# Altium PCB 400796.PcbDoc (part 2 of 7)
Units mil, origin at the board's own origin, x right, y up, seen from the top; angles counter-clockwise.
Board outline 2086.61 x 2086.61 mil, 6 copper layers (Top Layer, Mid Layer 1, Mid Layer 2, Mid Layer 3, Mid Layer 4, Bottom Layer), stack 58.818 mil thick; 313 components, 234 nets, 1244 pads, 2538 vias.
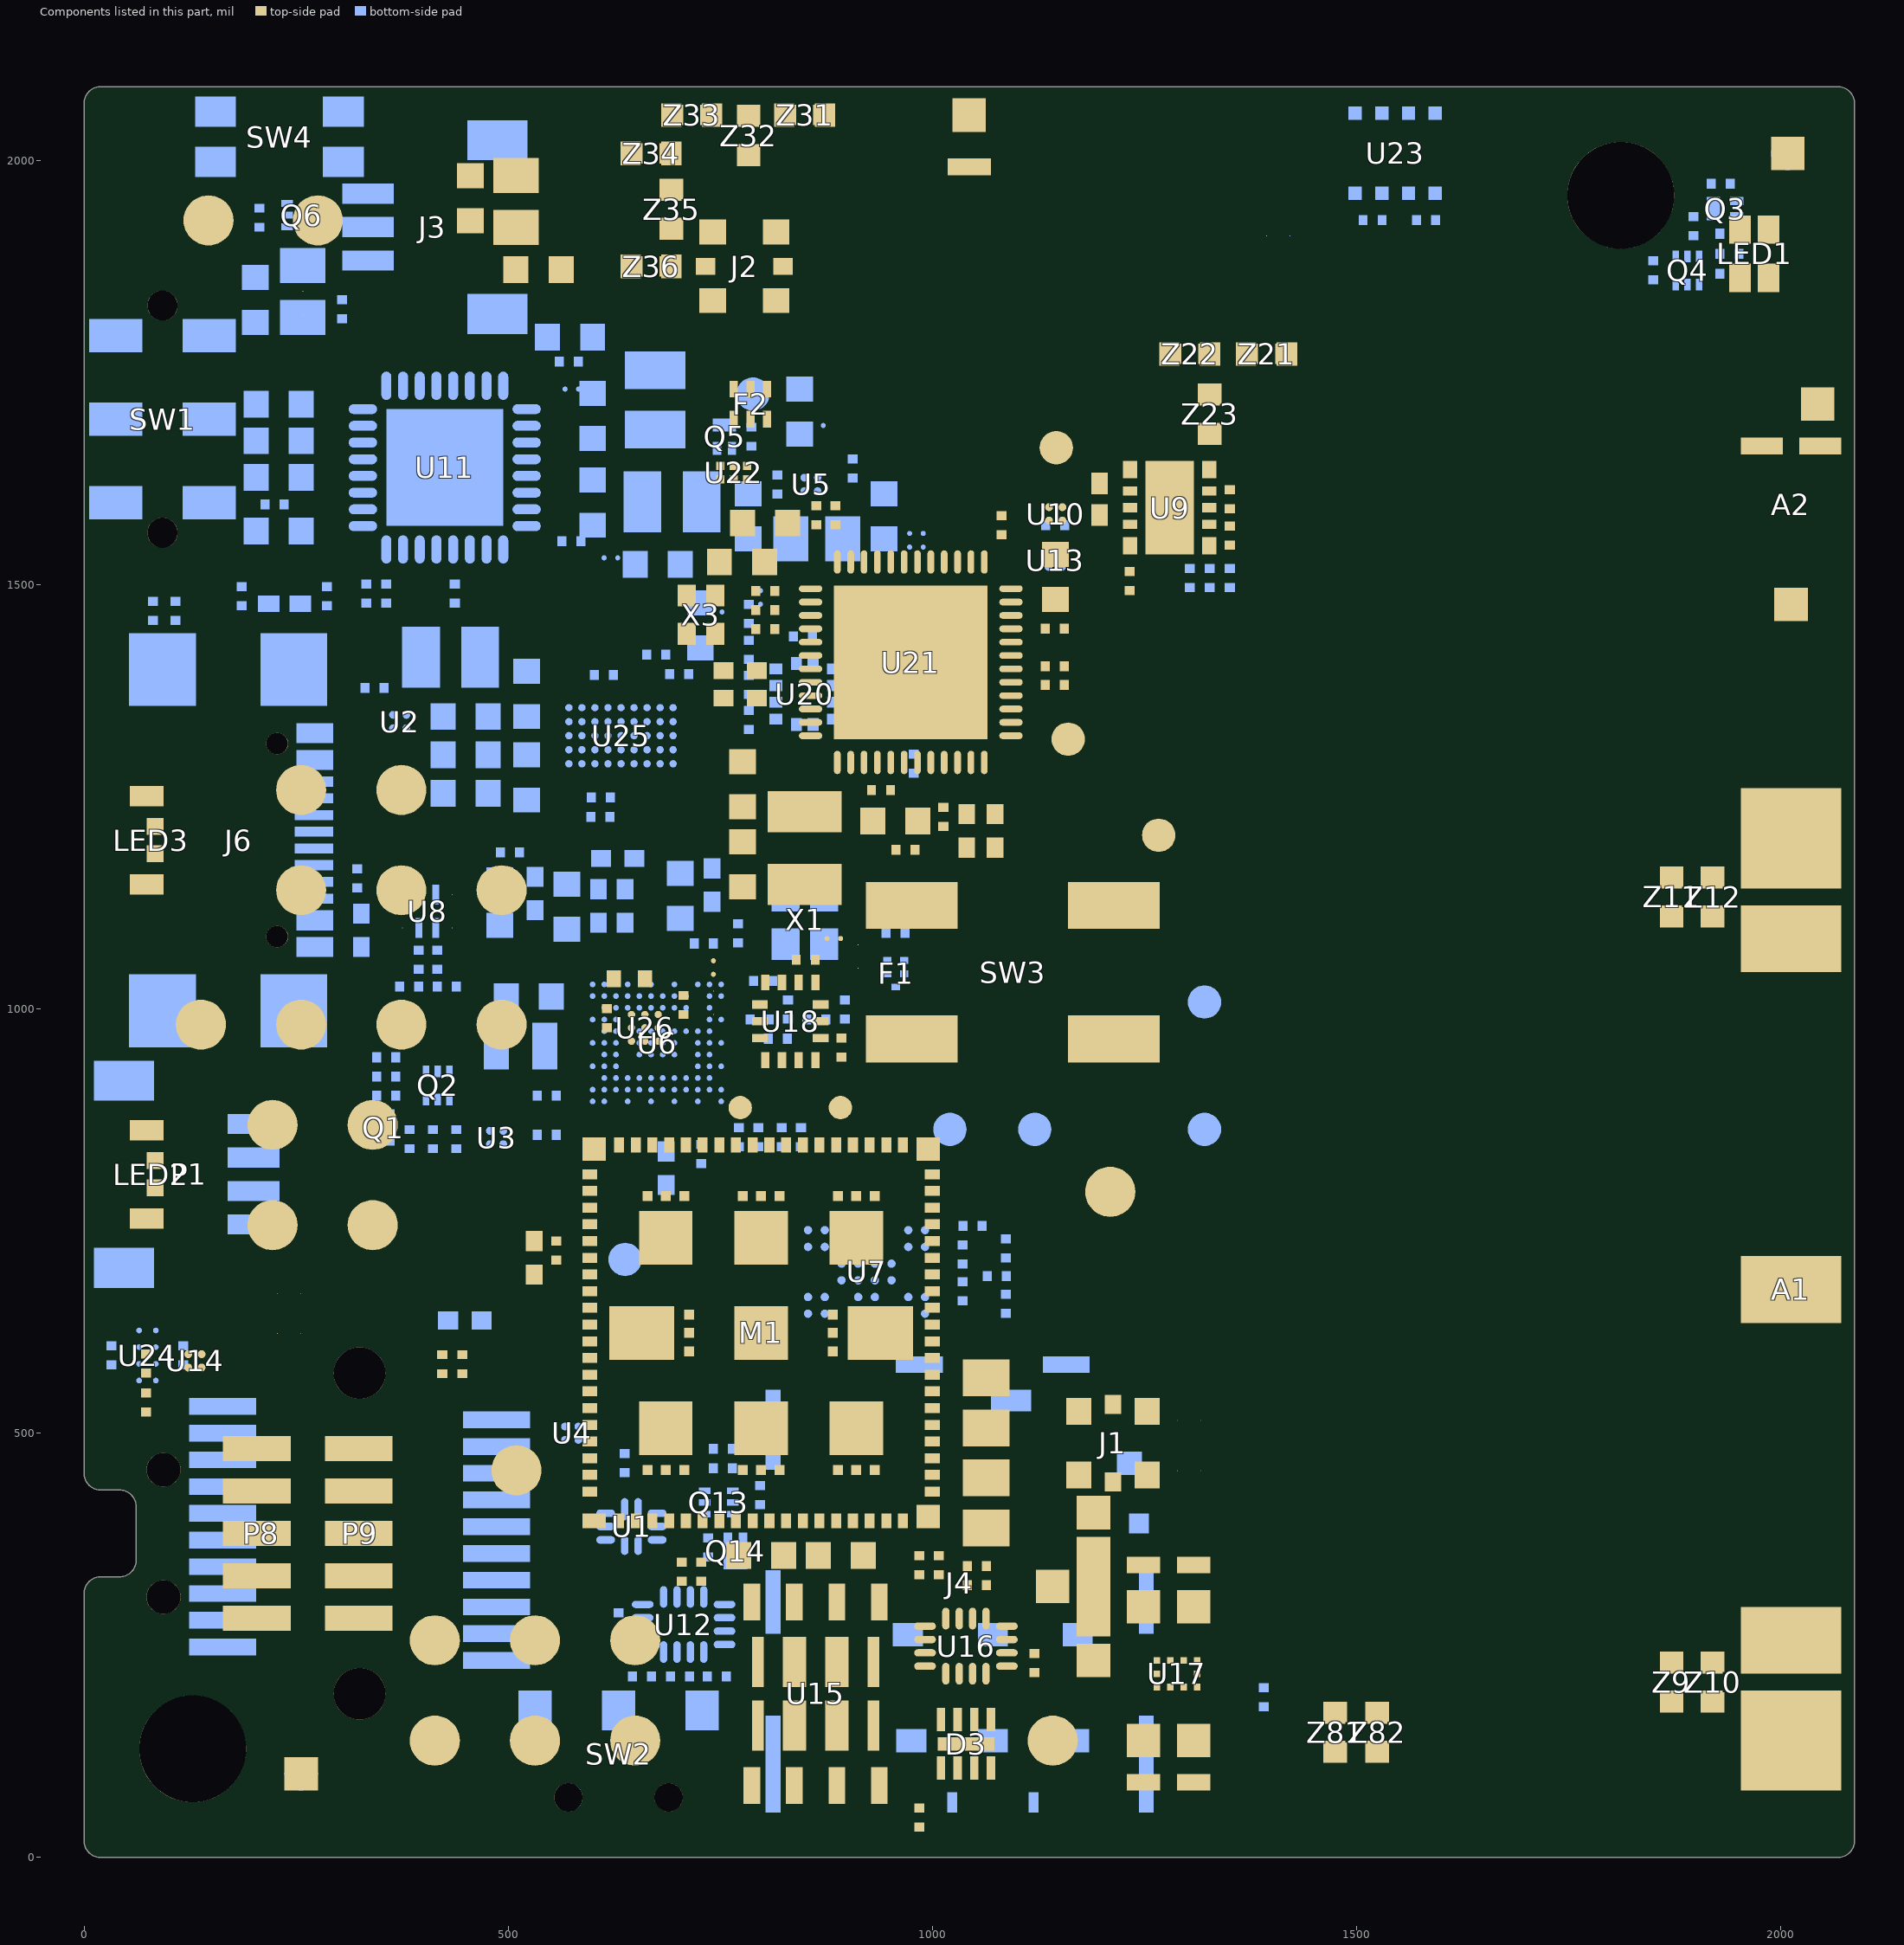
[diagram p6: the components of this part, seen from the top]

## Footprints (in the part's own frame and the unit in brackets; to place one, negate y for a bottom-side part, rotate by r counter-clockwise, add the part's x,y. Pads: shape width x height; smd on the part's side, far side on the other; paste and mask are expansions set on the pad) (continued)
COAXIAL-SWF [mm]
  rect 0.5x0.58 smd: 1(0,1.16) 3(0,-1.16)
  rect 0.75x0.8 smd: 2(-1.025,-0.95) 2(-1.025,0.95) 2(1.025,-0.95) 2(1.025,0.95)
  Top Layer pour cut-out: 0.65,-0.55 -0.65,-0.55 -0.65,-1.35 0.65,-1.35
  Top Layer pour cut-out: -0.65,0.55 0.65,0.55 0.65,1.35 -0.65,1.35
  silkscreen extent -1.25,-1.25 1.25,1.25, body extent -1.26,-1.3 1.26,1.3, height 1.55
DFN65P100X40-3L [mm] "DFN, 3-Leads, Body 0.60x1.00mm, Pitch 0.65mm, IPC High Density"
  rect 0.4x0.25 smd mask+0.05: 1(-0.35,0.225) 2(-0.35,-0.225)
  rect 0.4x0.7 smd mask+0.065: 3(0.35,0)
  silkscreen extent -0.57,0.58 -0.48,0.67, body extent -0.53,-0.33 0.53,0.33, height 0.4
Fiducial_Round-Square [mm] "Fiducial Mark"
  rect 1x1 smd paste-2539.97 mask+0.5: 0(0,0)
  round 1 smd far side paste-2539.97 mask+0.5: 0(0,0)
  Top Layer keep-out lines w0.01: 1,1 -1,1 -1,-1 1,-1 1,1
  Bottom Layer keep-out circle w0.01: c0,0 r1
HDR_2x5-SMD-1.27mm-ANG [mm] "Pin Header Angled, 1.27mm SMD, FTSH-105 series, \"SWD\" version"
  round 1.02 hole 1.02 unplated: 0(-1.905,-4.32) 0(1.905,-4.32)
  rect 0.76x2.03 smd: 1(-2.54,-1.525) 2(-2.54,1.525) 3(-1.27,-1.525) 4(-1.27,1.525) 5(0,-1.525) 6(0,1.525) 7(1.27,-1.525) 8(1.27,1.525) 9(2.54,-1.525) 10(2.54,1.525)
  silkscreen extent -3.17,-5.57 3.17,-3.07, body extent -3.17,-8.63 3.17,2.27, height 3.41
INDC0603X03L_C [mm] "Chip Inductor, 2-Leads, Body 0.6x0.3mm, IPC High Density"
  rect 0.27x0.3 smd: 1(-0.285,0) 2(0.285,0)
  silkscreen extent -0.49,-0.22 0.49,0.22, body extent -0.31,-0.16 0.31,0.16, height 0.26
INDC1005X04L [mm] "Chip Inductor, 2-Leads, Body 1.0x0.5mm, IPC High Density"
  rect 0.65x0.5 smd: 1(-0.475,0) 2(0.475,0)
  silkscreen extent -0.9,-0.35 0.9,0.35, body extent -0.5,-0.28 0.5,0.32, height 0.5
INDC1005X04L_WW [mm] "Chip Inductor, 2-Leads, Body 1.0x0.5mm, IPC High Density"
  rect 0.65x0.5 smd: 1(-0.475,0) 2(0.475,0)
  silkscreen extent -0.9,-0.35 0.9,0.35, body extent -0.5,-0.3 0.5,0.3, height 0.51
INDC1608X06L [mm] "Chip Inductor, 2-Leads, Body 1.6x0.8mm, IPC High Density"
  rect 0.75x0.8 smd: 1(-0.675,0) 2(0.675,0)
  silkscreen extent -1.17,-0.5 1.17,0.5, body extent -0.8,-0.4 0.8,0.4, height 0.8
INDC2012X11L [mm] "Chip Inductor, 2-Leads, Body 2.0x1.3mm, IPC High Density"
  rect 1.05x1.35 smd: 1(-0.775,0) 2(0.775,0)
  silkscreen extent -1.43,-0.77 1.43,0.77, body extent -1,-0.63 1,0.63, height 1.25
INDC2016X10N [mm] "Chip Inductor, 2-Leads, Body 2.00x1.60mm, IPC Medium Density"
  rect 1.13x1.82 smd: 1(-0.885,0) 2(0.885,0)
  silkscreen extent -1.65,-1.14 1.65,1.14, body extent -1.1,-0.9 1.1,0.9, height 1
INDC2520X10N [mm] "Chip Inductor, 2-Leads, Body 2,50x2,00mm, IPC Medium Density"
  rect 1.23x2.22 smd: 1(-1.085,0) 2(1.085,0)
  silkscreen extent -0.1,-1.01 0.1,1.01, body extent -1.25,-1.1 1.25,1.1, height 1.98
L-KLS7-TS5401A-1.35-250-T [mm]
  rect 1.225x0.9 smd: 1(-1.913,0.75) 1(1.913,0.75) 2(-1.913,-0.75) 2(1.913,-0.75)
  silkscreen extent -2.1,-2.15 1.75,1.84
L-KLS7-TS6616B-2.5-160-T [mm] "6.2×6.4mm TACT Switch, without ground connector"
  rect 2.75x1.4 smd: 1(-3.025,2) 1(3.025,2) 2(-3.025,-2) 2(3.025,-2)
  silkscreen extent -3,-3 3,3, body extent -3.6,-3.1 3.6,3.1, height 2.5
LabelSilk_12x38 [mil] "PCA version label, stick-on, 12x38mm"
  silkscreen extent 0,0 1496,472, body extent 0,-2 1496,472
LED_RGB_0606 [mm]
  rect 0.65x0.85 smd paste+0: 1(-0.425,0.725) 2(0.425,0.725) 3(0.425,-0.725) 4(-0.425,-0.725)
  silkscreen extent -0.75,-0.8 0.75,0.8, body extent -0.75,-0.8 0.75,0.8, height 0.35
LGA50P220X230X97-12N [mm] "LGA, 12-Leads, Body 2,20x2,30mm, Pitch 0,50mm, IPC Medium Density"
  rect 0.39x0.33 smd mask+0.05: 1(-0.86,0.75) 2(-0.86,0.25) 3(-0.86,-0.25) 4(-0.86,-0.75) 7(0.86,-0.75) 8(0.86,-0.25) 9(0.86,0.25) 10(0.86,0.75)
  rect 0.33x0.39 smd mask+0.05: 5(-0.25,-0.91) 6(0.25,-0.91) 11(0.25,0.91) 12(-0.25,0.91)
  silkscreen extent -1.4,-1.17 1.13,1.45, body extent -1.15,-1.2 1.15,1.2, height 0.97
"LGA50P1210X1110X130-113N - 98A0113SP002-O01" [mm]
  rect 0.7x0.45 smd paste-2539.97 mask-5: 1(-5,-5.625)
  rect 0.3x0.45 smd mask+0.05: 2(-4.25,-5.625) 3(-3.75,-5.625) 4(-3.25,-5.625) 5(-2.75,-5.625) 6(-2.25,-5.625) 7(-1.75,-5.625) 8(-1.25,-5.625) 9(-0.75,-5.625) 10(-0.25,-5.625) 11(0.25,-5.625) 12(0.75,-5.625) 13(1.25,-5.625) 14(1.75,-5.625) 15(2.25,-5.625) 16(2.75,-5.625) 17(3.25,-5.625) 18(3.75,-5.625) 19(4.25,-5.625) 42(4.25,5.625) 43(3.75,5.625) 44(3.25,5.625) 45(2.75,5.625) 46(2.25,5.625) 47(1.75,5.625) 48(1.25,5.625) 49(0.75,5.625) 50(0.25,5.625) 51(-0.25,5.625) 52(-0.75,5.625) 53(-1.25,5.625) 54(-1.75,5.625) 55(-2.25,5.625) 56(-2.75,5.625) 57(-3.25,5.625) 58(-3.75,5.625) 59(-4.25,5.625)
  rect 0.7x0.7 smd mask+0.05: 20(5,-5.5) 41(5,5.5) 60(-5,5.5)
  rect 0.45x0.3 smd mask+0.05: 21(5.125,-4.75) 22(5.125,-4.25) 23(5.125,-3.75) 24(5.125,-3.25) 25(5.125,-2.75) 26(5.125,-2.25) 27(5.125,-1.75) 28(5.125,-1.25) 29(5.125,-0.75) 30(5.125,-0.25) 31(5.125,0.25) 32(5.125,0.75) 33(5.125,1.25) 34(5.125,1.75) 35(5.125,2.25) 36(5.125,2.75) 37(5.125,3.25) 38(5.125,3.75) 39(5.125,4.25) 40(5.125,4.75) 61(-5.125,4.75) 62(-5.125,4.25) 63(-5.125,3.75) 64(-5.125,3.25) 65(-5.125,2.75) 66(-5.125,2.25) 67(-5.125,1.75) 68(-5.125,1.25) 69(-5.125,0.75) 70(-5.125,0.25) 71(-5.125,-0.25) 72(-5.125,-0.75) 73(-5.125,-1.25) 74(-5.125,-1.75) 75(-5.125,-2.25) 76(-5.125,-2.75) 77(-5.125,-3.25) 78(-5.125,-3.75) 79(-5.125,-4.25) 80(-5.125,-4.75)
  rect 0.3x0.3 smd mask+0.05: 81(-3.4,-4.1) 82(-2.85,-4.1) 83(-2.3,-4.1) 84(-0.55,-4.1) 85(0,-4.1) 86(0.55,-4.1) 87(2.3,-4.1) 88(2.85,-4.1) 89(3.4,-4.1) 90(2.15,-0.55) 91(2.15,0) 92(2.15,0.55) 93(3.4,4.1) 94(2.85,4.1) 95(2.3,4.1) 96(0.55,4.1) 97(0,4.1) 98(-0.55,4.1) 99(-2.3,4.1) 100(-2.85,4.1) 101(-3.4,4.1) 102(-2.15,0.55) 103(-2.15,0) 104(-2.15,-0.55)
  rect 1.6x1.6 smd mask+0.05: 105(-2.85,-2.85) 106(0,-2.85) 107(2.85,-2.85) 109(2.85,2.85) 110(0,2.85) 111(-2.85,2.85) 113(0,0)
  rect 1.95x1.6 smd mask+0.05: 108(3.575,0) 112(-3.575,0)
  Top Layer region: -5.35,-5.15 -5.35,-5.85 -4.65,-5.85 -4.65,-5.4 -4.9,-5.15
  silkscreen extent -5.99,-6.5 -5.69,-6.2, body extent -5.6,-6.1 5.6,6.1, height 1.21
MountingHole_3.2_M3 [mm] "Mounting hole, 3.2mm, M3,no annular"
  round 3.2 hole 3.2 unplated mask+0: ""(0,0)
NN02-101_Corner [mm] "NANO mXTEND  Miniature and high-efficiency Bluetooth/WI-FI Antenna"
  rect 0.5x1.3 smd mask+0.075: 0(-0.65,0)
  rect 1x1 smd mask+0.075: 1(0.9,0)
  Top Layer region: 0.4,-0.5 1.4,-0.5 1.4,0.5 0.4,0.5
  Multi-Layer pour cut-out: -3.25,-4 -3.25,1 1.75,1 1.75,-4
  silkscreen extent -1.32,-1.07 1.83,1.08, body extent -1.25,-1 1.75,1, height 0.8
NN03-310_RF_ALT1 [mm] "NN03-310_RF"
  rect 2x3 smd: 0(0,0) 2(10.5,0) 4(-10.5,0)
  rect 3x3 smd: 1(13.5,0) 3(-13.5,0)
  Top Layer region: 14,-0.5 15,-0.5 15,-6.504 14,-6.504
  Top Layer region: 13,-0.5 12,-0.5 12,-4 13,-4
  Top Layer region: 11.5,-0.5 10.5,-0.5 10.5,-4 11.5,-4
  Top Layer region: -12,-0.5 -13,-0.5 -13,-4 -12,-4
  Top Layer region: -10.5,-0.5 -11.5,-0.5 -11.5,-4 -10.5,-4
  Multi-Layer pour cut-out: -25,2 25,2 25,-10.5 -25,-10.5
  silkscreen extent -15,-1.6 15,1.6, body extent -15,-1.5 15,1.5, height 1
NN03-320 [mm]
  rect 1x1 smd: 1(-3,0) 4(3,-0.8)
  rect 0.5x1.25 smd: 2(1.75,-0.875) 3(1.75,0.875)
  Multi-Layer pour cut-out: -3.5,1.5 3.5,1.5 3.5,-1.5 -3.5,-1.5
  silkscreen extent -3.6,-1.6 3.6,1.6, body extent -3.5,-1.5 3.5,1.5, height 2.01
Nordic_QFN50P500X500X90-33N [mm] "QFN32 5x5x0.85mm, 0.5mm pitch - Medium Density"
  oval 0.85x0.3 smd mask+0.076: 1(-2.45,1.75) 2(-2.45,1.25) 3(-2.45,0.75) 4(-2.45,0.25) 5(-2.45,-0.25) 6(-2.45,-0.75) 7(-2.45,-1.25) 8(-2.45,-1.75) 17(2.45,-1.75) 18(2.45,-1.25) 19(2.45,-0.75) 20(2.45,-0.25) 21(2.45,0.25) 22(2.45,0.75) 23(2.45,1.25) 24(2.45,1.75)
  oval 0.3x0.85 smd mask+0.076: 9(-1.75,-2.45) 10(-1.25,-2.45) 11(-0.75,-2.45) 12(-0.25,-2.45) 13(0.25,-2.45) 14(0.75,-2.45) 15(1.25,-2.45) 16(1.75,-2.45) 25(1.75,2.45) 26(1.25,2.45) 27(0.75,2.45) 28(0.25,2.45) 29(-0.25,2.45) 30(-0.75,2.45) 31(-1.25,2.45) 32(-1.75,2.45)
  rect 3.5x3.5 smd: 33(0,0)
  silkscreen extent -3.43,-2.57 2.57,2.62, body extent -2.5,-2.5 2.5,2.5, height 0.9
OVSRRGBCC3_Side [mil] "Optek's OVSRRGBCC3 RGB full-color 1204 SMD, RGB LED"
  rect 20x20 smd: 1(5,-16) 2(5,16)
  rect 40x24 smd: 3(-5,52) 4(-5,-52)
  silkscreen extent -68,-68 18,68, body extent -65,-63 16,63, height 31
PQFN40P110X150X50-10N [mm] "PQFN, 10-Leads, Body 1,10x1,50mm, Pitch 0,40mm, IPC Medium Density"
  rect 0.2x0.2 smd mask+0.05: 1(-0.4,0.6) 2(-0.4,0.2) 3(-0.4,-0.2) 4(-0.4,-0.6) 5(0,-0.6) 6(0.4,-0.6) 7(0.4,-0.2) 8(0.4,0.2) 9(0.4,0.6) 10(0,0.6)
  silkscreen extent -0.9,-0.8 0.6,1.1, body extent -0.55,-0.75 0.55,0.75, height 0.5
QFN40P600X600X60-48N [mm] "QFN, 48-Leads, Body 6.1x6.1mm (max), Pitch 0.40mm, IPC Medium Density"
  oval 0.7x0.2 smd: 1(-3,2.2) 2(-3,1.8) 3(-3,1.4) 4(-3,1) 5(-3,0.6) 6(-3,0.2) 7(-3,-0.2) 8(-3,-0.6) 9(-3,-1) 10(-3,-1.4) 11(-3,-1.8) 12(-3,-2.2) 25(3,-2.2) 26(3,-1.8) 27(3,-1.4) 28(3,-1) 29(3,-0.6) 30(3,-0.2) 31(3,0.2) 32(3,0.6) 33(3,1) 34(3,1.4) 35(3,1.8) 36(3,2.2)
  oval 0.2x0.7 smd: 13(-2.2,-3) 14(-1.8,-3) 15(-1.4,-3) 16(-1,-3) 17(-0.6,-3) 18(-0.2,-3) 19(0.2,-3) 20(0.6,-3) 21(1,-3) 22(1.4,-3) 23(1.8,-3) 24(2.2,-3) 37(2.2,3) 38(1.8,3) 39(1.4,3) 40(1,3) 41(0.6,3) 42(0.2,3) 43(-0.2,3) 44(-0.6,3) 45(-1,3) 46(-1.4,3) 47(-1.8,3) 48(-2.2,3)
  rect 4.6x4.6 smd: 49(0,0)
  silkscreen extent -4.02,-3.05 3.05,3.05, body extent -3.02,-3.02 3.02,3.02, height 0.86
RESC0603X03L_C [mm] "Chip Resistor, 2-Leads, Body 0.6x0.3mm, IPC High Density"
  rect 0.27x0.3 smd: 1(-0.285,0) 2(0.285,0)
  silkscreen extent -0.49,-0.22 0.49,0.22, body extent -0.3,-0.15 0.3,0.15, height 0.23
RESC0603X03L_C_NC [mm] "Chip Resistor, 2-Leads, Body 0.6x0.3mm, IPC High Density"
  rect 0.27x0.3 smd: 1(-0.285,0) 2(0.285,0)
  silkscreen extent -0.49,-0.22 0.49,0.22
RESC1005X04L [mm] "Chip Resistor, 2-Leads, Body 1.0x0.5mm, IPC High Density"
  rect 0.6x0.55 smd mask+0.05: 1(-0.5,0) 2(0.5,0)
  silkscreen extent -0.87,-0.38 0.88,0.38, body extent -0.5,-0.25 0.5,0.25, height 0.3
SAFFB2G45MA0F0A [mm] "SOT23, 5-Leads, Body 2,90x2,80mm, Pitch 0,95mm, IPC Medium Density"
  rect 0.2x0.25 smd mask+0.065: 1(-0.4,0) 2(0,-0.25) 3(0.4,-0.25) 4(0.4,0.25) 5(0,0.25)
  silkscreen extent -0.81,-0.71 0.61,0.51, body extent -0.55,-0.45 0.55,0.45, height 0.5
SF72S006VBxR2500 [mm]
  rect 0.45x2.9 smd: 0(-11.175,1.9) 0(0,1.9)
  rect 0.45x1.9 smd: 0(-11.175,6.75) 0(0,6.75)
  rect 0.75x0.7 smd: 0(-10.675,10.9)
  rect 1.4x0.5 smd: 0(-8.78,13.85) 0(-4.38,13.85)
  rect 0.3x0.6 smd: 0(-7.8,0.75) 0(-5.36,0.75)
  rect 0.45x2.4 smd: 0(0,11.9)
  rect 0.9x0.7 smd: C1(-4.14,2.6) C2(-6.58,2.6) C3(-9.02,2.6) C5(-4.04,5.77) C6(-6.58,5.77) C7(-9.12,5.77)
  rect 0.6x0.6 smd: CSW(-10.95,9.1)
  rect 1.2x0.65 smd: DSW(-7.13,12.775)
  Top Layer pour cut-out: -10.084,9.5 -3.073,9.5 -3.073,-0.025 -10.084,-0.025
  Top Layer pour cut-out: -8.407,13.106 -3.48,13.106 -3.48,9.855 -8.407,9.855
  Top Layer keep-out region: -3.531,2.091 -3.531,3.107 -3.073,3.107 -3.073,2.091
  Top Layer keep-out region: -3.429,5.266 -3.429,6.282 -3.073,6.282 -3.073,5.266
  Top Layer keep-out region: -8.407,2.091 -8.407,3.107 -7.188,3.107 -7.188,2.091
  Top Layer keep-out region: -5.969,2.091 -5.969,3.107 -4.75,3.107 -4.75,2.091
  Top Layer keep-out region: -5.969,5.266 -5.969,6.282 -4.648,6.282 -4.648,5.266
  Top Layer keep-out region: -8.509,5.266 -8.509,6.282 -7.188,6.282 -7.188,5.266
  Top Layer keep-out region: -7.468,0.262 -7.468,1.278 -5.69,1.278 -5.69,0.262
  Top Layer keep-out region: -8.4,9.85 -8.4,13.099 -7.899,13.1 -7.899,12.302 -6.375,12.302 -6.375,13.1 -3.48,13.106 -3.48,9.855
  Top Layer keep-out region: -10.084,-0.025 -10.084,9.5 -3.073,9.5 -3.073,6.282 -9.728,6.282 -9.728,5.266 -3.073,5.266 -3.073,3.107 -9.627,3.107 -9.627,2.091 -3.073,2.091 -3.073,1.202 -8.128,1.202 -8.128,0.287 -5.029,0.287 -5.029,1.253 -3.073,1.253 -3.073,-0.025
  silkscreen extent -11.3,-0.67 0.67,14.53, body extent -11.2,0.05 0.02,14.4, height 1.25
SKY65943-11 [mm]
  rect 0.425x0.515 smd mask+0.05: 1(-1.188,1.144) 5(-1.188,-1.144) 6(1.188,-1.144) 10(1.188,1.144)
  rect 0.425x0.275 smd mask+0.05: 2(-1.188,0.5) 3(-1.188,0) 4(-1.188,-0.5) 7(1.188,-0.5) 8(1.188,0) 9(1.188,0.5)
  rect 1.45x2.802 smd paste-2 mask-5: 11(0,0)
  rect 1.55x2.487 on Top Solder: ""(0,0)
  Top Layer region: -0.988,0.887 -0.713,0.887 -0.713,1.4 -0.988,1.4
  Top Layer region: 0.713,-1.4 0.988,-1.4 0.988,-0.887 0.713,-0.887
  Top Layer region: 0.713,0.362 0.988,0.362 0.988,0.637 0.713,0.637
  Top Layer region: -0.712,-0.362 -0.987,-0.362 -0.987,-0.637 -0.712,-0.637
  silkscreen extent -1.65,-1.3 1.3,1.65, body extent -1.25,-1.25 1.25,1.25, height 0.71
SM03B-SRSS-TB [mm] "JST, SH connector, side entry SMD, 1mm pitch"
  rect 1.2x1.8 smd: 0(-2.6,-3.875) 0(2.6,-3.875)
  rect 0.6x1.55 smd: 1(-1,0) 2(0,0) 3(1,0)
  silkscreen extent -2.57,-4.67 2.57,-0.3, body extent -2.5,-4.6 2.5,0.35, height 2.96
SM04B-SRSS-TB [mm]
  rect 1.2x1.8 smd: 0(-2.8,0) 0(2.8,0)
  rect 0.6x1.55 smd: 1(-1.5,3.875) 2(-0.5,3.875) 3(0.5,3.875) 4(1.5,3.875)
  silkscreen extent -3,-0.7 3,3.55, body extent -3,-0.7 3,4.25, height 2.96
Solderbridge [mil]
  round 1 smd paste-99999: 1(-13.78,0) 2(13.78,0)
  Top Layer region: -7.49,19.36 -15.76,15.74 -21.55,8.8 -23.62,0 -23.62,0 -21.55,-8.79 -15.76,-15.74 -7.49,-19.36 -7.49,-19.36 -6.18,-19.31 -5.02,-18.71 -4.22,-17.68 -3.94,-16.4 -3.94,-16.4 -3.94,16.4 -4.22,17.68 -5.02,18.71 -6.18,19.31 -7.49,19.36
  Top Layer region: 7.49,-19.36 15.76,-15.74 21.55,-8.8 23.62,0 23.62,0 21.55,8.79 15.76,15.74 7.49,19.36 7.49,19.36 6.18,19.31 5.02,18.71 4.22,17.68 3.94,16.4 3.94,16.4 3.94,-16.4 4.22,-17.68 5.02,-18.71 6.18,-19.31 7.49,-19.36
Solderbridge_Shorted [mil]
  round 1 smd paste-99999: 1(-13.78,0) 2(13.78,0)
  Top Layer region: -4.92,3.94 -4.92,-3.94 4.92,-3.94 4.92,3.94
  Top Layer region: -7.49,19.36 -15.76,15.74 -21.55,8.8 -23.62,0 -23.62,0 -21.55,-8.79 -15.76,-15.74 -7.49,-19.36 -7.49,-19.36 -6.18,-19.31 -5.02,-18.71 -4.22,-17.68 -3.94,-16.4 -3.94,-16.4 -3.94,16.4 -4.22,17.68 -5.02,18.71 -6.18,19.31 -7.49,19.36
  Top Layer region: 7.49,-19.36 15.76,-15.74 21.55,-8.8 23.62,0 23.62,0 21.55,8.79 15.76,15.74 7.49,19.36 7.49,19.36 6.18,19.31 5.02,18.71 4.22,17.68 3.94,16.4 3.94,16.4 3.94,-16.4 4.22,-17.68 5.02,-18.71 6.18,-19.31 7.49,-19.36
SON50P210X160X65_HS-9N [mm] "SON, 8-Leads, Body 2.10x1.60mm, Pitch 0.50mm, Thermal Pad 1.70x0.4mm, IPC Medium Density"
  rect 0.7x0.25 smd mask+0.05: 1(-0.725,0.75) 2(-0.725,0.25) 3(-0.725,-0.25) 4(-0.725,-0.75) 5(0.725,-0.75) 6(0.725,-0.25) 7(0.725,0.25) 8(0.725,0.75)
  rect 0.4x1.7 smd paste-2 mask+0.05: 9(0,0)
  rect 0.3x0.75 on Top Paste: ""(0,0.425) ""(0,-0.425)
  silkscreen extent -1.26,-1.17 0.92,1.26, body extent -0.85,-1.1 0.85,1.1, height 0.65
SON127P600X90_HS-8N [mm] "SON, 8-Leads, Body 5.00x6.00mm, Pitch 1.27mm, IPC Medium Density"
  rect 1.5x0.35 smd: 0(-0.95,1.73) 0(-0.95,-1.73) 0(0.95,1.73) 0(0.95,-1.73)
  rect 1.5x0.7 smd: 0(-0.95,0.635) 0(-0.95,-0.635) 0(0.95,0.635) 0(0.95,-0.635)
  rect 1.1x0.5 smd: 1(-2.75,1.905) 2(-2.75,0.635) 3(-2.75,-0.635) 4(-2.75,-1.905) 5(2.75,-1.905) 6(2.75,-0.635) 7(2.75,0.635) 8(2.75,1.905)
  silkscreen extent -3.6,-2.58 3.08,2.73
SOTFL35P100X50-6N [mm] "SOTFL, 6-Leads, Body 1.00x1.00mm, Pitch 0.35mm, IPC Medium Density"
  rect 0.35x0.2 smd mask+0.05: 1(-0.425,0.35) 2(-0.425,0) 3(-0.425,-0.35) 4(0.425,-0.35) 5(0.425,0) 6(0.425,0.35)
  silkscreen extent -0.67,-0.57 0.43,0.72, body extent -0.5,-0.52 0.5,0.52, height 0.5
Switch-Slide-RA-J-Lead-DPDT-8.5x3.5mm [mm] "Slide Switches - DPDT, SMD, ON-ON"
  round 0.9 hole 0.9 unplated mask+0: 0(-3.4,0) 0(3.4,0)
  rect 1x1.6 smd: 1(-2.5,-1.4) 2(0,-1.4) 3(2.5,-1.4) 4(-2.5,1.4) 5(0,1.4) 6(2.5,1.4)
  silkscreen extent -4.5,-2.1 4.5,1.75, body extent -4.25,-3.75 4.25,1.75, height 3.5
TP_SMD_D0.7mm [mm] "Test point - pad 0.7mm"
  round 0.7 smd paste-5: 1(0,0)
  silkscreen extent -0.63,-0.64 0.63,0.63
TP_SMD_D1.0mm [mm] "Test point - pad 1.0mm"
  round 1 smd paste-5: 1(0,0)
  silkscreen extent -0.76,-0.76 0.76,0.76
TP_SMD_D1.5mm [mm] "Test point - pad 1.5mm"
  round 1.5 smd paste-5: 1(0,0)
  silkscreen extent -0.95,-0.95 0.95,0.95, body extent -0.75,-0.75 0.75,0.75, height 0.05
TSNP-6-8 [mm] "LGA, 6-Leads, Body 0,70x1,10mmx0,38mm, Pitch 0,40mm"
  rect 0.25x0.25 smd paste-0.03: 1(-0.2,0.4) 2(-0.2,0) 3(-0.2,-0.4) 4(0.2,-0.4) 5(0.2,0) 6(0.2,0.4)
  silkscreen extent -0.6,-0.8 0.6,0.8, body extent -0.38,-0.58 0.38,0.58, height 0.38
UFDFN50P120X250X55-8N [mm]
  round 0.025 smd: 1(-0.5,0.75) 4(-0.5,-0.75) 5(0.5,-0.75) 8(0.5,0.75)
  rect 0.6x0.2 smd: 2(-0.5,0.25) 3(-0.5,-0.25) 6(0.5,-0.25) 7(0.5,0.25)
  Top Layer region: 0.8,-0.85 0.4,-0.85 0.4,-1.05 0.2,-1.05 0.2,-0.65 0.8,-0.65
  Top Layer region: -0.2,-1.05 -0.4,-1.05 -0.4,-0.85 -0.8,-0.85 -0.8,-0.65 -0.2,-0.65
  Top Layer region: 0.4,0.85 0.8,0.85 0.8,0.65 0.2,0.65 0.2,1.05 0.4,1.05
  Top Layer region: -0.2,0.65 -0.8,0.65 -0.8,0.85 -0.4,0.85 -0.4,1.05 -0.2,1.05
  silkscreen extent -1.08,-1.37 0.6,1.37, body extent -0.6,-1.25 0.6,1.25, height 0.6
UFQFN40P140X180X55-10N [mm] "QFN, 10-Leads, Body 1.40x1.80mm, Pitch 0.40mm, IPC Medium Density"
  oval 0.663x0.225 smd mask+0.055: 1(-0.519,0.2)
  oval 0.563x0.225 smd mask+0.055: 2(-0.569,-0.2) 6(0.569,-0.2) 7(0.569,0.2)
  oval 0.225x0.563 smd mask+0.055: 3(-0.4,-0.769) 4(0,-0.769) 5(0.4,-0.769) 8(0.4,0.769) 9(0,0.769) 10(-0.4,0.769)
  silkscreen extent -1.15,-0.97 0.78,0.97, body extent -0.71,-0.91 0.71,0.91, height 0.55
USB4110 [mm] "USB TYPE C RECEPTACLE, 16 PIN"
  round 0.65 hole 0.65 unplated: 0(-2.89,0) 0(2.89,0)
  rect 0.6x1.1 smd mask+0.075: A1(-3.2,1.125) A4(-2.4,1.125) A9(2.4,1.125) A12(3.2,1.125)
  rect 0.3x1.15 smd mask+0.075: A5(-1.25,1.1) A6(-0.25,1.1) A7(0.25,1.1) A8(1.25,1.1) B5(1.75,1.1) B6(0.75,1.1) B7(-0.75,1.1) B8(-1.75,1.1)
  rect 2.18x2 smd: SHLD(-5.11,-3.43) SHLD(-5.11,0.5) SHLD(5.11,-3.43) SHLD(5.11,0.5)
  Top Layer region: -2.9,0.575 -3.015,0.561 -3.125,0.525 -3.125,0.525 -3.5,0.525 -3.5,0.7 -2.9,0.7
  Top Layer region: -2.7,0.543 -2.678,0.534 -2.655,0.525 -2.655,0.525 -2.1,0.525 -2.1,0.7 -2.7,0.7
  Top Layer region: 2.9,0.575 3.015,0.561 3.125,0.525 3.125,0.525 3.5,0.525 3.5,0.7 2.9,0.7
  Top Layer region: 2.7,0.543 2.678,0.534 2.655,0.525 2.655,0.525 2.1,0.525 2.1,0.7 2.7,0.7
  silkscreen extent -4.47,-5.6 4.47,-0.75, body extent -5.65,-6.28 5.65,1.42, height 3.26
WEE_3x4.5mm [mil]
  silkscreen extent -58,-106 58,67
XQFN40P180X260X50-16N [mm] "QFN, 16-Leads, Body 1.80x2.60mm, Pitch 0.40mm, IPC Medium Density"
  oval 0.65x0.22 smd paste-0.02 mask+0.04: 1(-0.825,0.6) 2(-0.825,0.2) 3(-0.825,-0.2) 4(-0.825,-0.6) 9(0.825,-0.6) 10(0.825,-0.2) 11(0.825,0.2) 12(0.825,0.6)
  oval 0.22x0.65 smd paste-0.02 mask+0.04: 5(-0.6,-1.225) 6(-0.2,-1.225) 7(0.2,-1.225) 8(0.6,-1.225) 13(0.6,1.225) 14(0.2,1.225) 15(-0.2,1.225) 16(-0.6,1.225)
  silkscreen extent -1.45,-1.4 1,1.4, body extent -0.91,-1.31 0.91,1.31, height 0.55
XTAL_2012 [mm] "XTAL SMD 2.0 x 1.2 mm"
  rect 0.75x1.4 smd: 1(-0.725,0) 2(0.725,0)
  silkscreen extent -0.24,-0.6 0.24,0.6, body extent -1,-0.61 1,0.61, height 0.6

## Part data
A1: library part NN03-310-R, "Mobile IoT LTE Multi-Band Antenna", Manufacturer=Ignion, Part number IPS=80000001819, Part number NEMS=100700053, Part number Norautron=N.A.
A2: "Dual-Band GNSS and Wi-Fi/BluetoothAntenna", Manufacturer=Ignion, Part number IPS=N.A., Part number NEMS=100700066, Supplier Part Number 1=2115-NN03-320CT-ND
A3: library part NN02-101_Corner, "Miniature and high-efficiency Bluetooth/Wi-Fi antenna", Manufacturer=Ignion, Part number IPS=N.A., Part number NEMS=100700077, Supplier Part Number 1=2115-NN02-101-ND
C1: library part C0201-15p, "Capacitor, NP0, ±5%, 25V", Manufacturer=Murata, Manufacturer Part Number=GRM0335C1E150JA01D, Part number IPS=00000003193, Part number NEMS=100200034, Part number Norautron=N.A.
C2 C4 C7 C10 C12 C13 C19 C20 C21 C28 C33 C34 C35 C37 C40 C55 C56 C57 C79 C86 C87 C88: library part C0201-100n, "Capacitor, X5R, ±10%", Manufacturer=N.A., Part number IPS="00000001248, 00000002505", Part number NEMS=100200078, Part number Norautron=262071862
C3: library part C0805-47µ-10V, "Capacitor, X5R, ±20%, 10V", Manufacturer=Murata, Manufacturer Part Number=GRM21BR61A476ME15, Part number IPS=00000004759, Part number NEMS=100200288, Part number Norautron=N.A., Supplier Part Number 1=490-9961-1-ND
C5: library part C0402-4µ7, "Capacitor, X5R, ±20%", Manufacturer=N.A., Part number IPS="00000001251, 00000007165", Part number NEMS=100200193, Supplier Part Number 1=490-13252-1-ND
C6: library part C0805-4µ7, "Capacitor, X5R, ±10%, 16V", Manufacturer=N.A., Part number IPS=00000006289, Part number NEMS=100200284
C8: library part C0402-2µ2-10V-X7R-GRM155Z71A225KE44D, "Capacitor, Ceramic, X7R, ±10%, 10V", Manufacturer=Murata, Manufacturer Part Number=GRM155Z71A225KE44D, Part number IPS=N.A., Part number NEMS=100200653, Supplier Part Number 1=490-GRM155Z71A225KE44DTR-ND
C9 C58 C74: library part C0201-1n0, "Capacitor, X7R, ±10%, 25V", Manufacturer=N.A., Part number IPS=00000003206, Part number NEMS=100200056
C11 C44 C75 C76: library part C0201-100n-25V-X5R, "Capacitor, Ceramic, X5R, ±10%, 25V", Manufacturer=Murata, Manufacturer Part Number=GRM033R61E104KE14J, Part number IPS=N.A., Part number NEMS=100200459, Supplier Part Number 1=490-14571-1-ND
C14 C15 C16 C17 C22 C23 C29: library part C0402-1µ0-10V-X5R, "Capacitor, Ceramic, X5R, ±10%, 10V", Manufacturer=N.A., Part number NEMS=100200482
C18: library part C0201-2n2, "Capacitor, X7R, ±10%, 10V", Manufacturer=N.A., Part number IPS=00000001778, Part number NEMS=100200060, Part number Norautron=26470002
C24: library part C0201-0.7p-50V-C0G-GJM0335C1HR70WB01, "Capacitor, Ceramic, C0G, ±0.05pF, 50V", Manufacturer=Murata, Manufacturer Part Number=GJM0335C1HR70WB01D, Part number IPS=N.A., Part number NEMS=100200011, Supplier Part Number 1=490-17145-1-ND
C25 C59: library part C0201-N.C., "Not mounted", Manufacturer=N.A., Part number NEMS=100200001
C26: library part C0603-4µ7-10V-X7S, "Capacitor, X7S, ±10%, 10V", Manufacturer=N.A., Part number IPS=00000001779, Part number NEMS=100200351, Supplier Part Number 1=445-14258-1-ND
C27: library part C0603-4µ7-6.3V-X7R, "Capacitor, X7R, ±10%, 6.3V", Manufacturer="Samsung Electro-Mechanics America", Manufacturer Part Number=CL10B475KQ8NQNC, Part number IPS=00000002541, Part number NEMS=100200350, Part number Norautron=N.A., Supplier Part Number 1=1276-2087-1-ND
C30 C67: library part C0603-2µ2-16V-X7S-GRM188C71C225KE11, "Capacitor, Ceramic, 2.2µF 16V X7S 0603,±10%", Manufacturer=Murata, Manufacturer Part Number=GRM188C71C225KE11D, Part number IPS=N.A., Part number NEMS=100200490, Supplier Part Number 1=81-GRM188C71C225KE1D
C31: library part C0201-39p, "Capacitor, NP0, ±1%, 25V", Manufacturer=Murata, Manufacturer Part Number=GRM0335C1E390FA01D, Part number IPS=00000001668, Part number NEMS=100200039, Part number Norautron=N.A.
C32 C36 C38: library part C0201-100p, "Capacitor, NP0, ±2%, 25V", Manufacturer=Murata, Manufacturer Part Number=GRM0335C1E101GA01D, Part number IPS=00000007853, Part number NEMS=100200044, Part number Norautron=N.A.
C39 C91 C92 C93: library part C0201-100n-6.3V-X5R, "Capacitor, Ceramic, X5R, ±10%, 6.3V", Manufacturer=Murata, Manufacturer Part Number=GRM033R60J104KE19D, Part number IPS=N.A., Part number NEMS=100200451, Supplier Part Number 1=490-3167-1-ND
C41 C62: library part C0201-100n-16V-X7S-GRM033C71C104KE14, "Capacitor, Ceramic, 100nF 16V X7S 0201,±10%", Manufacturer=Murata, Manufacturer Part Number=GRM033C71C104KE14D, Part number IPS=N.A., Part number NEMS=100200494, Supplier Part Number 1=81-GRM33C71C104KE14D
C42: library part C0402-2µ2-25V-X5R-GRM155R61E225KE11, "Capacitor, Ceramic, 2.2µF 25V X5R 0402,±10%", Manufacturer=Murata, Manufacturer Part Number=GRM155R61E225KE11D, Part number IPS=N.A., Part number NEMS=100200492, Supplier Part Number 1=81-GRM155R61E225KE1D
C43: library part C0201-10n-25V-X5R, "Capacitor, Ceramic, X5R, ±10%, 25V", Manufacturer=Murata, Manufacturer Part Number=GRM033R61E103KA12D, Part number IPS=N.A., Part number NEMS=100200458, Supplier Part Number 1=490-7194-1-ND
C45: library part C0402-1µ0-16V-X6S-GRM155C81C105KE11D, "Capacitor, Ceramic, 1.0µF 16V X6S 0402,±10%", Manufacturer=Murata, Manufacturer Part Number=GRM155C81C105KE11D, Part number IPS=N.A., Part number NEMS=100200516, Supplier Part Number 1=490-12700-2-ND
C46 C50: library part C0603-1µ0-10V-X5R, "Capacitor, Ceramic, 1.0µF 10V X5R 0603,±10%", Manufacturer=N.A., Part number NEMS=100200528
C47 C48 C49 C52 C53 C89 C90: library part C0603-10µ, "Capacitor, X5R, ±20%", Manufacturer=N.A., Part number IPS=00000007785, Part number NEMS=100200275
C51: library part C0603-2.2µ-16V-X7R, "Capacitor, Ceramic, X7R, ±10%, 16V", Manufacturer="Taiyo Yuden", Manufacturer Part Number=EMK107BB7225KA-T, Part number IPS=N.A., Part number NEMS=100200439, Supplier Part Number 1=587-5835-2-ND
C54: library part C0201-10n, "Capacitor, X7R, ±10%", Manufacturer=N.A., Part number IPS=00000003480, Part number NEMS=100200067, Part number Norautron=26621779
C60 C61: library part C0201-470n-6.3V-X5R-GRM033R60J474KE90, "Capacitor, Ceramic, 0.47µF 6.3V X5R 0201,±10%", Manufacturer=Murata, Manufacturer Part Number=GRM033R60J474KE90D, Part number IPS=N.A., Part number NEMS=100200488, Supplier Part Number 1=490-10409-1-ND
C63 C64 C65 C68: library part C0603-4µ7-25V-X6S-GRM188C81E475KE11, "Capacitor, Ceramic, 4.7µF 25V X6S 0603,±10%", Manufacturer=Murata, Manufacturer Part Number=GRM188C81E475KE11D, Part number IPS=N.A., Part number NEMS=100200486, Supplier Part Number 1=490-7199-1-ND
C66: library part C0201-10n-16V-X7R-GRM033R71C103KE14, "Capacitor, Ceramic, 10nF 16V X7R 0201,±10%", Manufacturer=Murata, Manufacturer Part Number=GRM033R71C103KE14D, Part number IPS=N.A., Part number NEMS=100200491, Supplier Part Number 1=490-14453-1-ND
C69: library part C0201-22n-10V-X5R-GRM033R61A223KE84, "Capacitor, Ceramic, 22nF 10V X5R 0201,±10%", Manufacturer=Murata, Manufacturer Part Number=GRM033R61A223KE84D, Part number IPS=N.A., Part number NEMS=100200495, Supplier Part Number 1=81-GRM033R61A223KE4E
C70: library part C0201-220n-10V-X5R-GRM033R61A224KE90, "Capacitor, Ceramic, 0.22µF 10V X5R 0201, ±10%", Manufacturer=Murata, Manufacturer Part Number=GRM033R61A224KE90D, Part number IPS=N.A., Part number NEMS=100200487, Supplier Part Number 1=81-GRM33R61A224KE90D
C71: library part C0201-2µ2-10V-X5R-GRM033R61A225KE47, "Capacitor, Ceramic, 2.2µF 10V X5R 0201,±10%", Manufacturer=Murata, Manufacturer Part Number=GRM033R61A225KE47D, Part number IPS=N.A., Part number NEMS=100200496, Supplier Part Number 1=81-GRM033R61A225KE7D
C72: library part C0402-1µ0-10V-X7S-GRM155C71A105KE11, "Capacitor, Ceramic, 1.0µF 10V X7S 0402,±10%", Manufacturer=Murata, Manufacturer Part Number=GRM155C71A105KE11D, Part number IPS=N.A., Part number NEMS=100200497, Supplier Part Number 1=81-GRM155C71A105KE1J
C73: library part C0402-1µ0-35V-X5R-GRM155R6YA105KE11, "Capacitor, Ceramic, 1.0µF 35V X5R 0402,±10%", Manufacturer=Murata, Manufacturer Part Number=GRM155R6YA105KE11D, Part number IPS=N.A., Part number NEMS=100200489, Supplier Part Number 1=81-GRM155R6YA105KE1D
C77 C78 C80: library part C0603-10µ-10V-X7T-GRM188D71A106MA73, "Capacitor, X7T, ±20%, 10V", Manufacturer=Murata, Manufacturer Part Number=GRM188D71A106MA73D, Part number IPS=00000004696, Part number NEMS=100200414, Part number Norautron=N.A., Supplier Part Number 1=490-7200-1-ND
C81: library part C0603-4µ7, "Capacitor, X5R, ±10%, 6.3V", Manufacturer=N.A., Part number IPS=00000007783, Part number NEMS=100200274
C82 C83 C84 C85: library part C0201-1µ0, "Capacitor, X5R, ±10%", Manufacturer=N.A., Part number IPS=00000001723, Part number NEMS=100200084, Supplier Part Number 1=1276-6795-1-ND
C94 C95 C96 C97 C98: library part C0603-10µ-25V-X5R-CL10A106MA8NRNC, "Capacitor, X5R, ±20%, 25V", Manufacturer="Samsung Electro-Mechanics America", Manufacturer Part Number=CL10A106MA8NRNC, Part number IPS=00000009948, Part number NEMS=100200354, Part number Norautron=N.A., Supplier Part Number 1=1276-1869-1-ND
C99 C100 C101 C102: library part C0201-10p, "Capacitor, C0G, ±5%, 25V", Manufacturer=Murata, Manufacturer Part Number=GRM0335C1E100JA01D, Part number IPS=00000003191, Part number NEMS=100200032, Part number Norautron=N.A.
C103: library part C0603-10µ-10V-X6S, "Capacitor, X6S, ±10%", Manufacturer=N.A., Part number NEMS=100200470
CR1: "ESD Suppressor, 30V, 0.04pF", Manufacturer=Panasonic, Part number IPS=00000004437, Part number NEMS=101300173, Part number Norautron=N.A., Supplier Part Number 1=P122037CT-ND
D3: "ESD Protection and EMI Filter for SIM Card Interface", Manufacturer="Texas Instruments", Part number IPS=N.A., Part number NEMS=101900729, Supplier Part Number 1=296-28299-1-ND
F1: "2.4 GHz BPF", Manufacturer=Murata, Part number IPS="00000001784, 80000001660", Part number NEMS=100800023, Part number Norautron=N.A.
F2: library part LFD182G45DCJD247, "Signal Conditioning 2.4GHz and 5GHz Diplexer", Manufacturer=Murata, Part number IPS=N.A., Part number NEMS=100800026, Supplier Part Number 1=81-LFD182G45DCJD247
FB1: library part FB0402-120R@100M-700mA, "Ferrite Bead, 120 Ohm @ 100MHz, 700mA, 130 mOhm Max", Manufacturer=Murata, Manufacturer Part Number=BLM15AX121SN1, Part number IPS=00000004487, Part number NEMS=100300100, Part number Norautron=N.A., Supplier Part Number 1=490-5439-1-ND
FB2: library part FB0402-120R@100M-500mA, "Ferrite Bead, 120 Ohm @ 100MHz, 500mA, 250 mOhm Max", Manufacturer=Murata, Manufacturer Part Number=BLM15AG121SN1D, Part number IPS=00000009954, Part number NEMS=100300099, Part number Norautron=265230631, Supplier Part Number 1=490-1005-1-ND
FB3 FB4 FB5: library part FB0805-1k@100MHz-500mA, "Ferrite Bead, 1k Ohm @ 100MHz, 500mA, 280 mOhm Max", Manufacturer=Murata, Part number IPS=N.A., Part number NEMS=100300399, Supplier Part Number 1=490-1041-1-ND
Fid1 Fid2: library part Fid-Mark-Round-Square, "Fiducial Mark", Manufacturer=N.A., Part number NEMS=100500075
H1 H2: library part MountingHole_3.2_M3, "Mounting hole, 3.2mm, M3, no annular", Manufacturer=N.A., Part number NEMS=101200008
J1 J2: "Coaxial Connector with Switch", Manufacturer=Murata, Part number IPS=00000009955, Part number NEMS=100500400, Part number Norautron=26030338, Supplier Part Number 1=490-4981-1-ND
J3: library part SM03B-SRSS-TB, "1.0mm pitch connector side entry SMD", Manufacturer="JST Sales America Inc.", Manufacturer Part Number=SM03B-SRSS-TB(LF)(SN), Part number IPS=00000001785, Part number NEMS=100500605, Part number Norautron=26032360
J4: library part SF72S006VBDR2500, "n 8 (6 + 2) Position Card Connector NANO SIM Surface Mount, Right Angle Gold", Manufacturer="JAE Electronics", Part number IPS=N.A., Part number NEMS=100500780, Supplier Part Number 1=670-2967-1-ND
J6: library part USB4110-GF-A, "USB-C Receptacle, 16 Pin, USB 2.0", Manufacturer="Global Connector Technology", Part number IPS=N.A., Part number NEMS=100500735, Supplier Part Number 1=2073-USB4110-GF-A-1-ND
L1 L2: library part L0603-10µ, "Inductor, 80mA, ±10%", Manufacturer="Taiyo Yuden", Manufacturer Part Number=LBMF1608T100K, Part number IPS=00000007794, Part number NEMS=100300078, Part number Norautron=N.A., Supplier Part Number 1=587-1714-1-ND
L3 L4: library part L0201-2n2, "Chip Inductor", Manufacturer=N.A., Part number NEMS=100300017
L5: library part L0402-9n1-Wirewound-Murata, "Inductor, 540mA, ±2%, 140mΩ, Q=25", Manufacturer=Murata, Manufacturer Part Number=LQW15AN9N1G00, Part number IPS=00000002497, Part number NEMS=100300357, Part number Norautron=N.A., Supplier Part Number 1=490-6854-1-ND
L6: library part L1008-3µ3-LQM2HPN3R3MGCL, "Inductor, 1A, ±20%, 200mOhm", Manufacturer=Murata, Manufacturer Part Number=LQM2HPN3R3MGCL, Part number IPS=N.A., Part number NEMS=100300406, Supplier Part Number 1=490-12070-1-ND
L7 L8 L9: library part L0806-2µ2-2500mA-73mOhm-CIGT201610EH2R2MNE, "Inductor, Irms=2.5A, Isat=2.9A, ±20%, DCR=73mΩ", Manufacturer="Samsung Electro-Mechanics America", Manufacturer Part Number=CIGT201610EH2R2MNE, Part number IPS=N.A., Part number NEMS=100300400, Part number Norautron=26521789, Supplier Part Number 1=1276-6901-1-ND
L10: library part L0603-470n-1600mA-69mOhm-MCFK1608TR47M, "Inductor, Irms=1.6A, Isat=1.9A, ±20%, DCR=69mΩ", Manufacturer="Taiyo Yuden", Manufacturer Part Number=MCFK1608TR47M, Part number IPS=N.A., Part number NEMS=100300402, Supplier Part Number 1=587-5625-1-ND
LABEL1: library part Label_12x38, "PCA version label, stick-on, 12x38mm", Manufacturer="Ellco Etikett", Manufacturer Part Number=83019, Part number IPS=N.A., Part number NEMS=101200031
LED1: library part LTST-C19HE1WT, "RGB LED 1.60 mm x 1.60 mm SMD", Manufacturer=LITEON, Part number IPS=00000007798, Part number NEMS=101400093, Part number Norautron=N.A., Supplier Part Number 1=160-2162-1-ND
LED2 LED3: library part OVSRRGBCC3_Side, "Optek, Side mounted RGB 1204 SMD LED", Manufacturer=Optek, Manufacturer Part Number=OVSRRGBCC3, Part number IPS=N.A., Part number NEMS=101400026, Supplier Part Number 1=365-1410-1-ND
LOGO1: library part "WEEE Symbol 3x4.5mm", "WEEE Directive symbol", Manufacturer=N.A., Part number NEMS=101100006
M1: library part nRF9151-LACAADA, "Low power System-in-Package with integrated LTE-M/NB-IoT modem and GPS", Manufacturer="Nordic Semiconductor", Part number IPS=N.A., Part number NEMS=102000324
NT1 NT2 ST1 ST2 ST3 ST4 ST5 ST7 ST9: library part "2 pin starpoint", "Starpoint", Manufacturer=N.A., Part number NEMS=100500603
P1: "JST SR/SH 1.0mm 4-pin", Manufacturer="JST Sales America Inc.", Part number IPS=N.A., Part number NEMS=100500540
P8: library part "Pin Header 2x5 SMD, 1.27mm, Angled", "Pin Header 2x5, 1.27mm (50mil)", Manufacturer=WCON, Manufacturer Part Number=1325B-1205S0Z080CR04, Part number IPS=N.A., Part number NEMS=100500257
P9: library part 10056847-101LF, "0.8mm pitch, dual edge, right angle, SMD, card edge connector", Manufacturer=FCI, Part number IPS=N.A., Part number NEMS=100500633, Supplier Part Number 1=609-4943-1-ND
Q1 Q3 Q5 Q14: "N-Channel MOSFET, 20V, 1A, 470mOhm, 400mW", Manufacturer="Rohm Semiconductor", Part number IPS=00000009976, Part number NEMS=101300132, Part number Norautron=26320026, Supplier Part Number 1=RV2C010UNT2LCT-ND
Q2 Q4: library part DMN2990UDJ-7, "MOSFET, Dual N-Channel, 20V, 450mA, 990mOhm, 350mW", Manufacturer="Diodes Incorporated", Part number IPS=N.A., Part number NEMS=101300177, Supplier Part Number 1=DMN2990UDJ-7DICT-ND
Q6 Q13: library part DMC2990UDJ-7, "MOSFET, Dual N and P-Channel, 20V, 450mA/310mA, 990mOhm, 350mW", Manufacturer="Diodes Incorporated", Part number IPS=00000004489, Part number NEMS=101300174, Part number Norautron=26470028, Supplier Part Number 1=DMC2990UDJ-7DICT-ND
R1 R17 R106: library part R0201-10k, "Resistor, ±1%, 0.05W", Manufacturer=N.A., Part number IPS=00000001255, Part number NEMS=100100065, Part number Norautron=26107101
R2 R26: library part R0201-1k0, "Resistor, ±1%, 0.05W", Manufacturer=N.A., Part number IPS=00000005786, Part number NEMS=100100043
R3 R9 R30 R33 R38 R41 R42 R44 R45 R46 R49 R54: library part R0201-1M0, "Resistor, ±1%, 0.05W", Manufacturer=N.A., Part number IPS=00000001418, Part number NEMS=100100093, Part number Norautron=26107108
R4 R6 R16: library part R0201-150, "Resistor, ±1%, 0.05W", Manufacturer=N.A., Part number IPS=00000001420, Part number NEMS=100100029
R5 R11 R27 R28 R29 R31 R32 R34: library part R0201-0R, "Resistor, ±5%, 0.05W", Manufacturer=N.A., Part number IPS=00000003245, Part number NEMS=100100001
R7: library part R0201-47k, "Resistor, ±1%, 0.05W", Manufacturer=N.A., Part number IPS=00000001423, Part number NEMS=100100076
R8: library part R0201-330k, "Resistor, ±1%, 0.05W", Manufacturer=N.A., Part number IPS=00000001424, Part number NEMS=100100087
R10: library part R0201-2R2, "Resistor, ±1%, 0.05W", Manufacturer=N.A., Part number NEMS=100100006, Part number Norautron=26470029
R12 R19: library part R0201-100, "Resistor, ±1%, 0.05W", Manufacturer=N.A., Part number IPS=00000001794, Part number NEMS=100100027, Part number Norautron=26107004
R13 R14 R20 R21: library part R0201-39R, "Resistor, ±1%, 0.05W", Manufacturer=N.A., Part number IPS=00000001704, Part number NEMS=100100021
R15: library part R0201-4M7, "Resistor, ±1%, 0.05W", Manufacturer=N.A., Part number NEMS=100100101
R18 R43 R50 R53 R58 R59 R60 R61 R62 R64 R107: library part R0201-100k, "Resistor, ±1%, 0.05W", Manufacturer=N.A., Part number IPS=00000001419, Part number NEMS=100100080, Part number Norautron=26108487
R22 R23: library part R0201-4k7, "Resistor, ±1%, 0.05W", Manufacturer=N.A., Part number IPS=00000001706, Part number NEMS=100100061
R24: library part R0402-0R1, "Resistor, ±1%, 0.063W", Manufacturer=N.A., Part number IPS=00000001795, Part number NEMS=100100111, Supplier Part Number 1=311-.10PDKR-ND
R25 R56 R108: library part R0201-N.C., "Not mounted", Manufacturer=N.A., Part number NEMS=100100107
SB1 SBI2: Manufacturer=N.A., Part number NEMS=100500458
SB4 SB5 SB6 SB7 SB8 SB9 SB10: library part "Solderbridge Shorted", "Shorted Solderbridge", Manufacturer=N.A., Part number NEMS=100500459
SW1: library part Switch-Slide-RA-J-Lead-DPDT-8.5x3.5mm_Copal, "SMD slide Switch (ON-ON)", Manufacturer="Copal Electronics Inc", Manufacturer Part Number=CL-SB-22A-11T, Part number IPS=00000007811, Part number NEMS=101500038, Part number Norautron=26470017, Supplier Part Number 1=563-1340-1-ND
SW2: "Miniature slide switch, SPDT, Right-Angle, ON-ON, 12V, 100mA", Manufacturer=C&K, Part number IPS=00000002488, Part number NEMS=101500120, Part number Norautron=N.A., Supplier Part Number 1=401-2012-1-ND
SW3: library part L-KLS7-TS6616B-2.5-160-T, "Tactile Switch, SPNO, SMD, 160gf, 6.2x6.4x2.5mm", Manufacturer=KLS, Part number IPS=N.A., Part number NEMS="101500133, 101500001"
SW4: "Microminiature SMT Switch, Side Actuated", Manufacturer=Cabcon, Part number IPS=N.A., Part number NEMS=101500149
TP1 TP2 TP3 TP4 TP5 TP9 TP10 TP12 TP13 TP14 TP15 TP16 TP17 TP18 TP19 TP27 TP28 TP29 TP30 TP31 TP32 TP33 TP35 TP36: library part TP_SMD_Ø1.5MM, "1.5mm circular SMD testpad", Manufacturer="Nordic Semiconductor", Manufacturer Part Number=N.A., Part number NEMS=100500477
TP7 TP20: library part TP_SMD_Ø0.7MM, "0.7mm circular SMD testpad", Manufacturer="Nordic Semiconductor", Manufacturer Part Number=N.A., Part number NEMS=100500474
TP8 TP11 TP21 TP22 TP23 TP24 TP25 TP26 TP34: library part TP_SMD_Ø1.0MM, "1.0mm circular SMD testpad", Manufacturer="Nordic Semiconductor", Manufacturer Part Number=N.A., Part number NEMS=100500475
U1: "Dual-SPDT Analog Switch", Manufacturer="ON Semiconductor", Part number IPS=N.A., Part number NEMS=101900819, Supplier Part Number 1=NLAS5223BMNR2GOSCT-ND
U2 U3 U4 U10 U13 U14: "1.0 A Load Switch IC with Slew Rate Control Driver in Ultra Small Package", Manufacturer=Toshiba, Manufacturer Part Number=TCK106AG,LF, Part number IPS=00000004390, Part number NEMS=101900575, Part number Norautron=26500627, Supplier Part Number 1=TCK106AGLFTR-ND
U5: "1.0 A Load Switch IC with Slew Rate Control Driver in Ultra Small Package", Manufacturer=Toshiba, Manufacturer Part Number=TCK108AG,LF, Part number IPS=N.A., Part number NEMS=101900814, Supplier Part Number 1=TCK108AGLFCT-ND
U6: "Multi-protocol Bluetooth Low Energy, IEEE 802.15.4, ANT and 2.4GHz proprietary system-on-chip", Manufacturer="Nordic Semiconductor", Part number IPS=N.A., Part number NEMS=102000319
U7: "Quad Serial Flash, 256Mbit, 133MHz, 1.65V - 2.0V", Manufacturer=GigaDevice, Part number IPS=N.A., Part number NEMS=101900759, Supplier Part Number 1=363-GD25LE255ELIGR
U8: "2 Line Common mode filter with ESD protection for USB 2.0 interface", Manufacturer=STMicroelectronics, Part number IPS=N.A., Part number NEMS=100800034, Supplier Part Number 1=497-13420-2-ND
U9: "GNSS Low-Noise Amplifier Front-End Module with Integrated Pre-Filter and Post-Filter", Manufacturer=Skyworks, Part number IPS=00000002997, Part number NEMS=101900584, Part number Norautron=N.A., Supplier Part Number 1=863-2032-1-ND
U11: "Li-Ion/Li-Polymer USB-C battery charger with high efficiency buck regulators, LDOs or load switches, LED drivers, TWI and VBUSOUT", Manufacturer="Nordic Semiconductor", Part number IPS=N.A., Part number NEMS=102000333
U12: "Data / Audio Low-Voltage Dual DPDT Analog Switch", Manufacturer="ON Semiconductor", Part number IPS=00000009986, Part number NEMS=101900422, Part number Norautron=26500608, Supplier Part Number 1=FSA2466UMXCT-ND
U15: library part M2M_UICC, "M2M UICC SIM Card", Manufacturer=N.A., Part number NEMS=101900595
U16: library part NX3DV2567GU, "Low-ohmic four-pole double-throw analog switch", Manufacturer="NXP Semiconductors", Part number IPS=00000007816, Part number NEMS=101900290, Part number Norautron=N.A., Supplier Part Number 1=568-5206-1-ND
U17: "SP4T RF Switch with RFFE Interface", Manufacturer=Qorvo, Part number IPS=N.A., Part number NEMS=101900679
U18: "6-axis, smart, low-power, inertial measurement unit", Manufacturer=Bosch, Part number IPS=N.A., Part number NEMS=101900620, Supplier Part Number 1=828-1091-1-ND
U20: library part ADXL367BCCZ, "Micropower, 3-Axis, ±2 g/±4 g/±8 g Digital Output MEMS Accelerometer", Manufacturer="Analog Devices", Part number IPS=N.A., Part number NEMS=101900775, Supplier Part Number 1=505-ADXL367BCCZ-RL7CT-ND
U21: "Wi-fi Dual Band Companion chip", Manufacturer="Nordic Semiconductor", Part number IPS=N.A., Part number NEMS=102000276
U22: library part BGS12WN6E6327XTSA1, "Wideband SPDT RF Switch, 50MHz-6GHz. Max 26dBm, 1.65-3.6V", Manufacturer="Infineon Technologies", Part number IPS=N.A., Part number NEMS=101900784, Supplier Part Number 1=448-BGS12WN6E6327XTSA1CT-ND
U23: "Low power gas, pressure, temperature & humidity sensor", Manufacturer=Bosch, Part number IPS=N.A., Part number NEMS=101900619
U24: "Voltage Level Translator Bidirectional 1 Circuit 2 Channel 24Mbps 8-DSBGA", Manufacturer="Texas Instruments", Part number IPS=N.A., Part number NEMS=101900724, Supplier Part Number 1=296-TXS0102YZPRCT-ND
U25: "Low-power and high efficiency PMIC", Manufacturer="Nordic Semiconductor", Part number IPS=N.A., Part number NEMS=102000358
U26: "Magnetoresistive Sensor X, Y, Z Axis 9-WLCSP (1.28x1.28)", Manufacturer="Bosch Sensortec", Part number IPS=N.A., Part number NEMS=101900817, Supplier Part Number 1=828-BMM350CT-ND
X1: library part XTAL_SMD2016_32MHz_8pF_Kyocera_SA, "XTAL SMD 2016, 32MHz, Cl=8pF, ±30ppm, -40°C ~ 105°C", Manufacturer=Kyocera, Manufacturer Part Number=CX2016SA32000D0WRQG1, Part number IPS=N.A., Part number NEMS=101600100
X2: library part XTAL_SMD2012_32.768kHz_9pF_Golledge, "XTAL SMD 2012, 32.768kHz, 9pF, ±20ppm", Manufacturer=Golledge, Manufacturer Part Number=MP07668, Part number IPS=N.A., Part number NEMS=101600017, Part number Norautron=26470047
X3: library part XTAL_SMD1612_40MHz_8pF, "XTAL SMD 1612, 40MHz, Cl=8pF, Total Tol: ±10ppm", Manufacturer="Abracon Corporation", Manufacturer Part Number=ABM12W-40.0000MHZ-8-B1U-T3, Part number IPS=N.A., Part number NEMS=101600095, Supplier Part Number 1=535-13991-2-ND
Z1: library part C0402-6.0p-50V-NP0-GJM1555C1H6R0WB01, "Capacitor, NP0, ±0.05pF, 50V", Manufacturer=Murata, Manufacturer Part Number=GJM1555C1H6R0WB01D, Part number IPS=N.A., Part number NEMS=100200532, Supplier Part Number 1=490-11230-1-ND
Z2 Z5 Z7 Z23 Z81 Z82: library part R0603-0r, "Resistor, ±5%, 0.1W", Manufacturer=N.A., Part Number=R0603-0R, Part number NEMS=100100283
Z3: library part C0402-2.1p-50V-NP0-GJM1555C1H2R1WB01, "Capacitor, NP0, ±0.05pF, 50V", Manufacturer=Murata, Manufacturer Part Number=GJM1555C1H2R1WB01D, Part number IPS=N.A., Part number NEMS=100200533, Supplier Part Number 1=490-GJM1555C1H2R1WB01DCT-ND
Z4 Z6: library part L0402-3n7-1950mA-30mΩ-LQW15AN3N7G80, "Inductor, 1950mA, ±2%, 30mΩ, Q=35", Manufacturer=Murata, Manufacturer Part Number=LQW15AN3N7G80D, Part number IPS=N.A., Part number NEMS=100300421, Supplier Part Number 1=81-LQW15AN3N7G80D
Z9: library part C0402-0.3p-HQ-Murata, "Capacitor, NP0, ±0.05pF, 50V", Manufacturer=Murata, Manufacturer Part Number=GJM1555C1HR30WB01D, Part number IPS=00000001777, Part number NEMS=100200433, Part number Norautron=N.A., Supplier Part Number 1=490-11248-1-ND
Z10: library part L0603-12n-750mA-71mΩ-LQW18AN12NG10, "Inductor, 750mA, ±2%, 71mΩ, Q=38", Manufacturer=Murata, Manufacturer Part Number=LQW18AN12NG10, Part number IPS=N.A., Part number NEMS=100300414, Supplier Part Number 1=490-6862-1-ND
Z11 Z32: library part C0402-N.C., "Not mounted", Manufacturer=N.A., Part number NEMS=100200105
Z12: library part L0402-N.C., "Not mounted", Manufacturer=N.A., Part number NEMS=100300037
Z21: library part L0402-2n8-1500mA-47mΩ-LQW15AN2N8G80, "Inductor, 1500mA, ±2%, 47mΩ, Q=27", Manufacturer=Murata, Manufacturer Part Number=LQW15AN2N8G80D, Part number IPS=N.A., Part number NEMS=100300422, Supplier Part Number 1=81-LQW15AN2N8G80D
Z22: library part L0402-2n5-Wirewound-Murata-LQW15AN2N5G80, "Inductor, 2100mA, ±2%, 30mΩ, Q=30", Manufacturer=Murata, Manufacturer Part Number=LQW15AN2N5G80D, Part number IPS=N.A., Part number NEMS=100300417, Supplier Part Number 1=LQW15AN2N5G80D-ND
Z31: library part L0402-3n8-Wirewound-Murata_HQ-LQW15AN3N8G80D, "3.8 nH Unshielded Drum Core, Wirewound Inductor 1.95 A 30mOhm Max 0402 (1005 Metric)", Manufacturer=Murata, Manufacturer Part Number=LQW15AN3N8G80D, Part number IPS=N.A., Part number NEMS=100300486, Supplier Part Number 1=490-LQW15AN3N8G80DTR-ND
Z33: library part L0402-9n0-Wirewound-Murata_HQ-LQW15AN6N0B80D, "6 nH Unshielded Drum Core, Wirewound Inductor 1.6 A 56mOhm Max 0402 (1005 Metric)", Manufacturer=Murata, Manufacturer Part Number=LQW15AN6N0B80D, Part number IPS=N.A., Part number NEMS=100300487, Supplier Part Number 1=490-17896-1-ND
Z34: library part C0402-0.4p-50V-NP0-GJM1555C1HR40WB01, "Capacitor, NP0, ±0.05pF, 50V", Manufacturer=Murata, Manufacturer Part Number=GJM1555C1HR40WB01D, Part number IPS=N.A., Part number NEMS=100200500, Supplier Part Number 1=490-11249-1-ND
Z35: library part C0402-1.8p-HQ-Murata, "Capacitor, C0G, ±0.05pF, 50V", Manufacturer=Murata, Manufacturer Part Number=GJM1555C1H1R8WB01D, Part number IPS=N.A., Part number NEMS=100200521, Supplier Part Number 1=490-11202-1-ND
Z36: library part L0603-N.C., "Not mounted", Manufacturer=N.A., Part number NEMS=100300069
